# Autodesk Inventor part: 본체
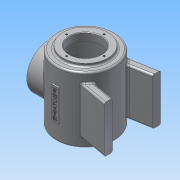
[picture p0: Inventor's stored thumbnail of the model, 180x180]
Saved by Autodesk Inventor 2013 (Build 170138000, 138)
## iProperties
Created: 2015-01
Part Number: 본체
Material: 알루미늄 6061
Document SubType Name: Modeling
Designer: Administrator
Density: 2.71089 g/cm^3
Mass: 1022 g
Surface Area: 1060.64 cm^2
Volume: 376.997 cm^3
Author: Administrator
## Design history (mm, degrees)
sketch "스케치1"
  geometry: C1 r 50 at (0, 0); 1 further point
  constraints: 1 centre point, 1 coincident
  dimensions: "d0" = 100 diameter of C1
extrude "돌출1" new body sketch "스케치1" stored distance "d1" = 112; taper "d2" = 0 deg
sketch "스케치2"
  geometry: C1 r 38 at (0, 0); 1 further point
  constraints: 1 centre point, 1 coincident
  dimensions: "d3" = 76 diameter of C1
extrude "돌출2" join sketch "스케치2" distance "d4" = 5; taper "d5" = 0 deg
sketch "스케치4"
  geometry: L1 (0, -48.5)-(45, -48.5); L2 (45, -48.5)-(45, 48.5); L3 (45, 48.5)-(0, 48.5); L4 (0, 48.5)-(0, -48.5); 2 further points
  constraints: 8 end point, 2 parallel, 1 coincident, 1 horizontal, 1 midpoint, 1 perpendicular
  dimensions: "d6" = 97 distance of L1.end L2.end; "d8" = 90 diameter of L2 L4
sketch "스케치6"
  geometry: C1 r 27 at (0, 0); 1 further point
  constraints: 1 centre point, 1 coincident
  dimensions: "d10" = 54 diameter of C1
extrude "돌출3" cut sketch "스케치6" stored distance "d11" = 5; taper "d12" = 0 deg
node "작업 평면1"
sketch "스케치7"
  geometry: C1 r 38 at (0, 0); 1 further point
  constraints: 1 centre point, 1 coincident
  dimensions: "d14" = 76 diameter of C1
extrude "돌출4" join sketch "스케치7" stored distance "d15" = 5; taper "d16" = 0 deg
sketch "스케치8"
  geometry: C1 r 27 at (0, 0); 1 further point
  constraints: 1 centre point, 1 coincident
  dimensions: "d17" = 54 diameter of C1
extrude "돌출5" cut sketch "스케치8" stored distance "d18" = 5; taper "d19" = 0 deg
sketch "스케치9"
  geometry: 2 further points
  constraints: 1 vertical alignment
  dimensions: "d20" = 32 distance of point (0, 0) point (0, 32)
hole "구멍1" sketch "스케치9" at (0, 32) diameter "d21" = 3.242; stored, may be unused: countersink angle "d25" = 90 deg, drill point angle "d27" = 118 deg; dims "d22" = 8, "d23" = 4, "d24" = 2, "d26" = 10
sketch "스케치10"
  geometry: 2 further points
  constraints: 1 vertical alignment
  dimensions: "d31" = 32 distance of point (0, 32) point (0, 0)
hole "구멍2" sketch "스케치10" at (0, 32) diameter "d32" = 3.242; stored, may be unused: countersink angle "d36" = 90 deg, drill point angle "d38" = 118 deg; dims "d33" = 8, "d34" = 4, "d35" = 2, "d37" = 10
node "작업 평면3"
sketch "스케치11"
  geometry: L1 (-32.496, -38)-(-62, -38) reference; L2 (-62, -38)-(-62, -33.621) reference; L3 (-62, -33.621)-(-52, -33.621) reference; L4 (-52, -33.621)-(-51.026, -32) reference; L5 (-51.026, -32)-(-52, -30.379) reference; L6 (-52, -30.379)-(-62, -30.379) reference; L7 (-62, -30.379)-(-62, -27) reference; L8 (-62, -27)-(0, -27) reference; L9 (0, 27)-(-62, 27) reference; L10 (-62, 27)-(-62, 30.379) reference; L11 (-62, 30.379)-(-52, 30.379) reference; L12 (-52, 30.379)-(-51.026, 32) reference; L13 (-51.026, 32)-(-52, 33.621) reference; L14 (-52, 33.621)-(-62, 33.621) reference; L15 (-62, 33.621)-(-62, 38) reference; L16 (-62, 38)-(-32.496, 38) reference; L17 (80, 34.111)-(80, 48.111); L18 (80, 48.111)-(30.75, 39.427); L19 (80, 34.111)-(41.836, 27.381); A1 r 50 centre (0, 0) between (-32.496, -38) and (-32.496, 38) reference; A2 r 27 centre (0, 0) between (0, -27) and (0, 27) reference; 1 further point
  constraints: 6 end point, 2 point on circle, 1 parallel, 1 perpendicular
  dimensions: "d49" = 80 horizontal distance of L17.end point (0, 0); "d50" = 100 deg angle of L18 L17; "d53" = 14 distance of L17.start L17.end; "d54" = 38.16387 horizontal distance of L17.start L19.end
extrude "돌출6" join sketch "스케치11" stored distance "d55" = 80; taper "d56" = 0 deg
node "작업 평면4"
fillet "모깎기1" dims "d66" = 3
fillet "모깎기2" dims "d67" = 3
chamfer "모따기1" distance "d68" = 1; stored, may be unused: second distance "d69" = 2, angle "d70" = 45 deg
node "작업 평면6"
node "작업 평면7"
sketch "스케치16"
  geometry: L1 (6, -27)-(-6, -27); L2 (-6, -27)-(-6, 27); L3 (-6, 27)-(6, 27); L4 (6, 27)-(6, -27); L5 (6, -27)-(-6, 27); L6 (-6, -27)-(6, 27); 1 further point
  constraints: 12 end point, 2 midpoint, 2 parallel, 1 horizontal, 1 perpendicular
  dimensions: "d85" = 12 distance of L2.end L3.end; "d86" = 54 distance of L1.end L2.end
extrude "돌출8" join sketch "스케치16" stored distance "d87" = 10; taper "d88" = 0 deg
sketch "스케치17"
  geometry: L1 (38, -61)-(-38, -61) reference; 2 further points
  constraints: 2 coincident, 1 other
feature "엠보싱5" sketch "스케치17" dims "d90" = 0.5, "d91" = 0
node "작업 평면8"
sketch "스케치18"
  geometry: C1 r 45 at (0, 0); 1 further point
  constraints: 1 centre point, 1 coincident
  dimensions: "d93" = 90 diameter of C1
extrude "돌출9" cut sketch "스케치18" distance "d94" = 97; taper "d95" = 0 deg
fillet "모깎기4" dims "d96" = 3
node "솔리드1"
mirror "대칭1"
pattern_circular "원형 패턴1" dims angle "d29" = 360 deg
pattern_circular "원형 패턴2" dims angle "d40" = 360 deg
mirror "대칭2"
mirror "대칭3"
node "절단 모서리 투영1"
other parameters: "d13" = -62, "d84" = -2, "d92" = -12
